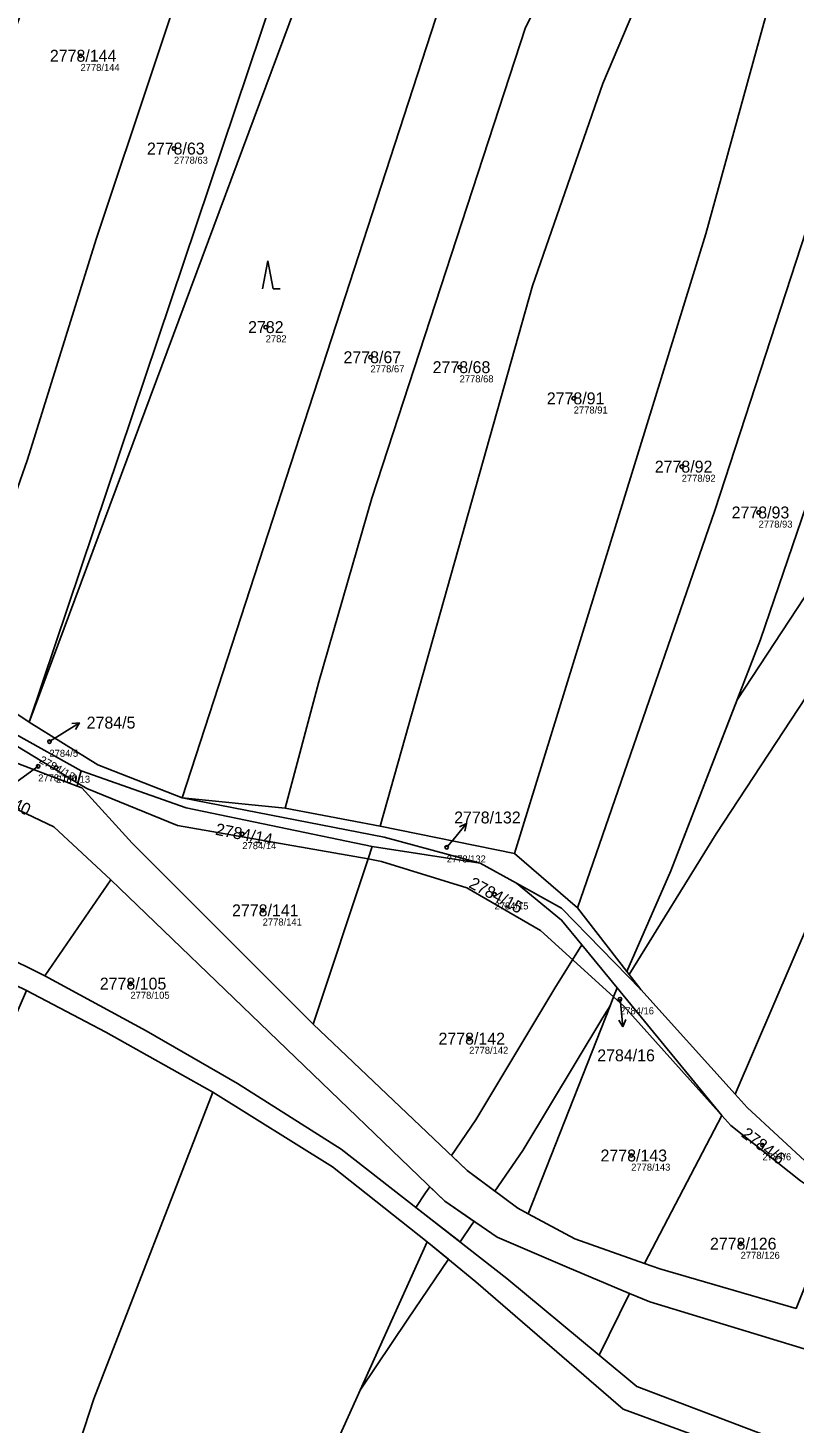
# Model space of a CAD drawing. Extents: x -739214 to -733252, y -1147612 to -1142842.
# Drawn here: x -737800.8 to -737691.6, y -1144174.3 to -1143975.5 of the extents above; entities that cross this region are included whole.
import ezdxf

# ---------------------------------------------------------------- set-up
doc = ezdxf.new("R2010")
doc.units = 0
for name, color, linetype in [('Definiční body', 7, 'Continuous'), ('Hranice parcel', 7, 'Continuous'), ('Parcelní čísla', 7, 'Continuous'), ('Polygon parcely', 7, 'Continuous'), ('Pop  PČ popisy', 7, 'Continuous'), ('Věcná břemena k části', 7, 'Continuous'), ('Značky kultur', 7, 'Continuous')]:
    doc.layers.add(name, color=color, linetype=linetype)

msp = doc.modelspace()

# ---------------------------------------------------------------- linework, layer by layer
at = {"layer": 'Definiční body'}
for centre in [(-737793.3, -1143979.46), (-737779.98, -1143992.68), (-737766.9, -1144018.12), (-737751.97, -1144022.41), (-737739.26, -1144023.83), (-737722.99, -1144028.27), (-737707.6, -1144038), (-737696.64, -1144044.53), (-737797.73, -1144077.18), (-737799.33, -1144080.69), (-737796.77, -1144080.88), (-737770.23, -1144090.34), (-737741.1, -1144092.24), (-737734.28, -1144098.93), (-737767.33, -1144101.22), (-737786.18, -1144111.66), (-737716.39, -1144113.87), (-737737.9, -1144119.5), (-737696.09, -1144134.67), (-737714.8, -1144136.15), (-737699.2, -1144148.71)]:
    msp.add_circle(centre, 0.25, dxfattribs=at)
at = {"layer": 'Hranice parcel'}
for p, q in [((-737811.43, -1144067.17), (-737800.62, -1144074.4)), ((-737802.59, -1144076.13), (-737793.21, -1144081.36)), ((-737793.79, -1144083.52), (-737803.83, -1144079.68)), ((-737793.68, -1144083.1), (-737793.21, -1144081.36)), ((-737793.79, -1144083.52), (-737793.68, -1144083.1)), ((-737778.79, -1144085.17), (-737764.11, -1144086.64)), ((-737764.11, -1144086.64), (-737750.57, -1144089.22)), ((-737750.57, -1144089.22), (-737731.44, -1144093.11)), ((-737752.31, -1144093.9), (-737751.72, -1144092.12)), ((-737751.72, -1144092.12), (-737736.33, -1144094.49)), ((-737760.15, -1144117.43), (-737752.31, -1144093.9)), ((-737731.44, -1144093.11), (-737722.45, -1144100.88)), ((-737736.33, -1144094.49), (-737731.14, -1144097.37)), ((-737788.99, -1144096.86), (-737798.39, -1144110.57)), ((-737722.45, -1144100.88), (-737715.43, -1144109.92)), ((-737715.43, -1144109.92), (-737713.43, -1144112.5)), ((-737717.31, -1144113.54), (-737716.81, -1144112.26)), ((-737716.81, -1144112.26), (-737701.87, -1144130.45)), ((-737713.43, -1144112.5), (-737700, -1144127.4)), ((-737701.87, -1144130.45), (-737712.92, -1144151.53)), ((-737715.02, -1144155.79), (-737719.36, -1144164.62))]:
    msp.add_line(p, q, dxfattribs=at)
for points in [[(-737753.56, -1143903.8), (-737763.28, -1143926.88), (-737774.4, -1143955.62), (-737791.08, -1144005.6), (-737800.85, -1144036.99), (-737811.43, -1144067.17)], [(-737747.42, -1143922.86), (-737762.04, -1143959.68), (-737800.62, -1144074.4)], [(-737731.19, -1143947.35), (-737747.9, -1143931.07), (-737755.39, -1143952.93), (-737800.62, -1144074.4)], [(-737778.79, -1144085.17), (-737742.03, -1143972.22), (-737731.19, -1143947.35)], [(-737764.11, -1144086.64), (-737759.35, -1144068.64), (-737751.79, -1144042.48), (-737729.89, -1143975.41), (-737721.43, -1143958.8)], [(-737750.57, -1144089.22), (-737728.86, -1144012.23), (-737718.85, -1143983.41), (-737711.46, -1143966.05)], [(-737731.44, -1144093.11), (-737704.16, -1144004.85), (-737695.11, -1143972.07)], [(-737722.45, -1144100.88), (-737702.88, -1144044.25), (-737679.03, -1143971.13)], [(-737715.43, -1144109.92), (-737709.14, -1144095.6), (-737696.36, -1144062.61), (-737675.57, -1144001.73), (-737665.81, -1143976.37)], [(-737700, -1144127.4), (-737689.12, -1144102.09), (-737672.1, -1144058.13), (-737645.71, -1143987.25)], [(-737800.62, -1144074.4), (-737790.82, -1144080.48), (-737778.79, -1144085.17)], [(-737793.68, -1144083.1), (-737802.5, -1144077.72), (-737803.03, -1144077.38)], [(-737832.85, -1144079.76), (-737811.85, -1144082.35), (-737797.08, -1144089.32), (-737788.99, -1144096.86)], [(-737793.21, -1144081.36), (-737778.24, -1144086.59), (-737751.72, -1144092.12)], [(-737760.15, -1144117.43), (-737785.94, -1144091.63), (-737793.11, -1144083.78), (-737793.79, -1144083.52)], [(-737752.31, -1144093.9), (-737779.49, -1144089.11), (-737792.4, -1144083.88), (-737793.68, -1144083.1)], [(-737778.79, -1144085.17), (-737750.03, -1144090.8), (-737736.33, -1144094.49)], [(-737717.31, -1144113.54), (-737727.72, -1144104.11), (-737738.21, -1144097.99), (-737750.41, -1144094.24), (-737752.31, -1144093.9)], [(-737835.66, -1144095.81), (-737817.39, -1144101.13), (-737798.39, -1144110.57)], [(-737788.99, -1144096.86), (-737741.37, -1144142.66), (-737733.92, -1144147.79), (-737723.93, -1144152.08), (-737715.02, -1144155.79)], [(-737731.14, -1144097.37), (-737724.72, -1144100.93), (-737713.43, -1144112.5)], [(-737731.14, -1144097.37), (-737724.73, -1144102.6), (-737721.85, -1144106.12), (-737716.81, -1144112.26)], [(-737798.39, -1144110.57), (-737783.92, -1144118.4), (-737770.91, -1144125.89), (-737756.13, -1144135.24), (-737732.54, -1144153.66), (-737719.36, -1144164.62)], [(-737774.46, -1144127.14), (-737789.7, -1144118.58), (-737800.98, -1144112.63)], [(-737729.47, -1144144.45), (-737717.81, -1144114.82), (-737717.31, -1144113.54)], [(-737701.87, -1144130.45), (-737715.85, -1144114.86), (-737717.31, -1144113.54)], [(-737729.47, -1144144.45), (-737730.96, -1144143.65), (-737738.16, -1144138.28), (-737760.15, -1144117.43)], [(-737774.46, -1144127.14), (-737791.38, -1144170.83), (-737800.92, -1144199.98), (-737804.43, -1144210.47), (-737815.21, -1144249.95), (-737823.77, -1144273.2)], [(-737743.89, -1144148.46), (-737757.36, -1144137.78), (-737774.46, -1144127.14)], [(-737700, -1144127.4), (-737698.26, -1144129.33), (-737689.43, -1144137.46), (-737683.21, -1144141.42)], [(-737685.37, -1144143.26), (-737690.67, -1144139.74), (-737700.6, -1144131.87), (-737701.87, -1144130.45)], [(-737712.92, -1144151.53), (-737722.85, -1144148), (-737729.47, -1144144.45)], [(-737743.89, -1144148.46), (-737756.47, -1144176.32), (-737774.04, -1144228.79), (-737783.15, -1144260.28), (-737791.71, -1144292.95)], [(-737696.15, -1144179.54), (-737715.96, -1144172.28), (-737736.94, -1144154.13), (-737743.89, -1144148.46)], [(-737691.29, -1144157.94), (-737710.74, -1144152.3), (-737712.92, -1144151.53)], [(-737715.02, -1144155.79), (-737712.12, -1144156.99), (-737655.52, -1144174.25)], [(-737719.36, -1144164.62), (-737714.01, -1144169.07), (-737692.22, -1144177.34), (-737663.62, -1144194.63), (-737660.98, -1144196.62)]]:
    msp.add_lwpolyline(points, dxfattribs=at)
at = {"layer": 'Polygon parcely'}
for points in [[(-737811.43, -1144067.17), (-737800.85, -1144036.99), (-737791.08, -1144005.6), (-737774.4, -1143955.62), (-737763.28, -1143926.88), (-737753.56, -1143903.8), (-737751.85, -1143900.08), (-737765.42, -1143893.22), (-737789.14, -1143941.15), (-737795.02, -1143954.63), (-737822.47, -1144030.56), (-737830.99, -1144056.18)], [(-737811.43, -1144067.17), (-737800.62, -1144074.4), (-737762.04, -1143959.68), (-737747.42, -1143922.86), (-737743.4, -1143912.94), (-737753.56, -1143903.8), (-737763.28, -1143926.88), (-737774.4, -1143955.62), (-737791.08, -1144005.6), (-737800.85, -1144036.99)], [(-737762.04, -1143959.68), (-737800.62, -1144074.4), (-737755.39, -1143952.93), (-737747.9, -1143931.07), (-737731.19, -1143947.35), (-737741.28, -1143934.28), (-737738.88, -1143928.91), (-737747.42, -1143922.86)], [(-737790.82, -1144080.48), (-737778.79, -1144085.17), (-737742.03, -1143972.22), (-737731.19, -1143947.35), (-737747.9, -1143931.07), (-737755.39, -1143952.93), (-737800.62, -1144074.4)], [(-737751.79, -1144042.48), (-737729.89, -1143975.41), (-737721.43, -1143958.8), (-737722.24, -1143957.09), (-737725.62, -1143952.53), (-737731.19, -1143947.35), (-737742.03, -1143972.22), (-737778.79, -1144085.17), (-737764.11, -1144086.64), (-737759.35, -1144068.64)], [(-737750.57, -1144089.22), (-737728.86, -1144012.23), (-737718.85, -1143983.41), (-737711.46, -1143966.05), (-737721.43, -1143958.8), (-737729.89, -1143975.41), (-737751.79, -1144042.48), (-737759.35, -1144068.64), (-737764.11, -1144086.64)], [(-737731.44, -1144093.11), (-737704.16, -1144004.85), (-737695.11, -1143972.07), (-737711.46, -1143966.05), (-737718.85, -1143983.41), (-737728.86, -1144012.23), (-737750.57, -1144089.22)], [(-737702.88, -1144044.25), (-737679.03, -1143971.13), (-737695.11, -1143972.07), (-737704.16, -1144004.85), (-737731.44, -1144093.11), (-737722.45, -1144100.88)], [(-737709.14, -1144095.6), (-737696.36, -1144062.61), (-737675.57, -1144001.73), (-737665.81, -1143976.37), (-737665.1, -1143974.47), (-737679.03, -1143971.13), (-737702.88, -1144044.25), (-737722.45, -1144100.88), (-737715.43, -1144109.92)], [(-737713.43, -1144112.5), (-737700, -1144127.4), (-737689.12, -1144102.09), (-737672.1, -1144058.13), (-737645.71, -1143987.25), (-737665.81, -1143976.37), (-737675.57, -1144001.73), (-737696.36, -1144062.61), (-737709.14, -1144095.6), (-737715.43, -1144109.92)], [(-737683.21, -1144141.42), (-737660.95, -1144082.54), (-737639.25, -1144021.37), (-737628.56, -1143994.6), (-737645.71, -1143987.25), (-737672.1, -1144058.13), (-737689.12, -1144102.09), (-737700, -1144127.4), (-737698.26, -1144129.33), (-737689.43, -1144137.46)], [(-737778.24, -1144086.59), (-737751.72, -1144092.12), (-737736.33, -1144094.49), (-737750.03, -1144090.8), (-737778.79, -1144085.17), (-737790.82, -1144080.48), (-737800.62, -1144074.4), (-737811.43, -1144067.17), (-737842.67, -1144053.64), (-737864.22, -1144045.97), (-737882.61, -1144037.94), (-737882.88, -1144041.39), (-737864.57, -1144046.82), (-737843.51, -1144054.24), (-737837.39, -1144056.82), (-737827.23, -1144061.07), (-737814.21, -1144069.2), (-737802.59, -1144076.13), (-737793.21, -1144081.36)], [(-737793.68, -1144083.1), (-737793.21, -1144081.36), (-737802.59, -1144076.13), (-737803.03, -1144077.38), (-737802.5, -1144077.72)], [(-737802.5, -1144077.72), (-737803.03, -1144077.38), (-737803.83, -1144079.68), (-737793.79, -1144083.52), (-737793.68, -1144083.1)], [(-737798.39, -1144110.57), (-737788.99, -1144096.86), (-737797.08, -1144089.32), (-737811.85, -1144082.35), (-737832.85, -1144079.76), (-737835.66, -1144095.81), (-737817.39, -1144101.13)], [(-737751.72, -1144092.12), (-737778.24, -1144086.59), (-737793.21, -1144081.36), (-737793.68, -1144083.1), (-737792.4, -1144083.88), (-737779.49, -1144089.11), (-737752.31, -1144093.9)], [(-737752.31, -1144093.9), (-737779.49, -1144089.11), (-737792.4, -1144083.88), (-737793.68, -1144083.1), (-737793.79, -1144083.52), (-737793.11, -1144083.78), (-737785.94, -1144091.63), (-737760.15, -1144117.43)], [(-737731.14, -1144097.37), (-737724.72, -1144100.93), (-737713.43, -1144112.5), (-737715.43, -1144109.92), (-737722.45, -1144100.88), (-737731.44, -1144093.11), (-737750.57, -1144089.22), (-737764.11, -1144086.64), (-737778.79, -1144085.17), (-737750.03, -1144090.8), (-737736.33, -1144094.49)], [(-737717.31, -1144113.54), (-737716.81, -1144112.26), (-737721.85, -1144106.12), (-737724.73, -1144102.6), (-737731.14, -1144097.37), (-737736.33, -1144094.49), (-737751.72, -1144092.12), (-737752.31, -1144093.9), (-737750.41, -1144094.24), (-737738.21, -1144097.99), (-737727.72, -1144104.11)], [(-737738.21, -1144097.99), (-737750.41, -1144094.24), (-737752.31, -1144093.9), (-737760.15, -1144117.43), (-737738.16, -1144138.28), (-737730.96, -1144143.65), (-737729.47, -1144144.45), (-737717.81, -1144114.82), (-737717.31, -1144113.54), (-737727.72, -1144104.11)], [(-737756.13, -1144135.24), (-737732.54, -1144153.66), (-737719.36, -1144164.62), (-737715.02, -1144155.79), (-737723.93, -1144152.08), (-737733.92, -1144147.79), (-737741.37, -1144142.66), (-737788.99, -1144096.86), (-737798.39, -1144110.57), (-737783.92, -1144118.4), (-737770.91, -1144125.89)], [(-737721.85, -1144106.12), (-737716.81, -1144112.26), (-737701.87, -1144130.45), (-737700.6, -1144131.87), (-737690.67, -1144139.74), (-737685.37, -1144143.26), (-737684.11, -1144144.1), (-737651.57, -1144160.64), (-737668.68, -1144150.65), (-737683.21, -1144141.42), (-737689.43, -1144137.46), (-737698.26, -1144129.33), (-737700, -1144127.4), (-737713.43, -1144112.5), (-737724.72, -1144100.93), (-737731.14, -1144097.37), (-737724.73, -1144102.6)], [(-737774.46, -1144127.14), (-737789.7, -1144118.58), (-737800.98, -1144112.63), (-737814.3, -1144143.39), (-737823.93, -1144167.59), (-737831.77, -1144190.63), (-737843.78, -1144222.11), (-737853.81, -1144251.92), (-737839.18, -1144262.99), (-737823.77, -1144273.2), (-737815.21, -1144249.95), (-737804.43, -1144210.47), (-737800.92, -1144199.98), (-737791.38, -1144170.83)], [(-737701.87, -1144130.45), (-737715.85, -1144114.86), (-737717.31, -1144113.54), (-737717.81, -1144114.82), (-737729.47, -1144144.45), (-737722.85, -1144148), (-737712.92, -1144151.53)], [(-737717.31, -1144113.54), (-737715.85, -1144114.86), (-737701.87, -1144130.45), (-737716.81, -1144112.26)], [(-737823.77, -1144273.2), (-737809.7, -1144282.52), (-737791.71, -1144292.95), (-737783.15, -1144260.28), (-737774.04, -1144228.79), (-737756.47, -1144176.32), (-737743.89, -1144148.46), (-737757.36, -1144137.78), (-737774.46, -1144127.14), (-737791.38, -1144170.83), (-737800.92, -1144199.98), (-737804.43, -1144210.47), (-737815.21, -1144249.95)], [(-737685.37, -1144143.26), (-737690.67, -1144139.74), (-737700.6, -1144131.87), (-737701.87, -1144130.45), (-737712.92, -1144151.53), (-737710.74, -1144152.3), (-737691.29, -1144157.94)], [(-737736.94, -1144154.13), (-737743.89, -1144148.46), (-737756.47, -1144176.32), (-737774.04, -1144228.79), (-737783.15, -1144260.28), (-737791.71, -1144292.95), (-737777.16, -1144298.24), (-737750.46, -1144304.05), (-737741.14, -1144306.42), (-737735.31, -1144283.15), (-737727.76, -1144259.01), (-737718.72, -1144233.73), (-737702.56, -1144192.49), (-737696.15, -1144179.54), (-737715.96, -1144172.28)], [(-737714.01, -1144169.07), (-737692.22, -1144177.34), (-737663.62, -1144194.63), (-737660.98, -1144196.62), (-737659.48, -1144193), (-737656.33, -1144177.29), (-737655.52, -1144174.25), (-737712.12, -1144156.99), (-737715.02, -1144155.79), (-737719.36, -1144164.62)]]:
    msp.add_lwpolyline(points, close=True, dxfattribs=at)
for points in [[(-737964.98, -1144037.92), (-737934.66, -1144053.55), (-737929.32, -1144055.23), (-737923.72, -1144055.39), (-737913.71, -1144055.05), (-737905.24, -1144054.77), (-737901.35, -1144056.29), (-737898.05, -1144058.59), (-737885.4, -1144069.1), (-737883.75, -1144069.88), (-737873.47, -1144074.76), (-737832.85, -1144079.76), (-737811.85, -1144082.35), (-737797.08, -1144089.32), (-737788.99, -1144096.86), (-737741.37, -1144142.66), (-737733.92, -1144147.79), (-737723.93, -1144152.08), (-737715.02, -1144155.79), (-737712.12, -1144156.99), (-737655.52, -1144174.25)], [(-737692.22, -1144177.34), (-737714.01, -1144169.07), (-737719.36, -1144164.62), (-737732.54, -1144153.66), (-737756.13, -1144135.24), (-737770.91, -1144125.89), (-737783.92, -1144118.4), (-737798.39, -1144110.57), (-737817.39, -1144101.13), (-737835.66, -1144095.81), (-737868.18, -1144087.54), (-737889.25, -1144085.28), (-737892.12, -1144085.08), (-737914.29, -1144076.59), (-737932.49, -1144068.97), (-737944.21, -1144063.75)], [(-737949.57, -1144066.24), (-737919.88, -1144077.7), (-737891.15, -1144088.14), (-737868.79, -1144090.89), (-737851.64, -1144094.91), (-737818.97, -1144103.97), (-737800.98, -1144112.63), (-737789.7, -1144118.58), (-737774.46, -1144127.14), (-737757.36, -1144137.78), (-737743.89, -1144148.46), (-737736.94, -1144154.13), (-737715.96, -1144172.28), (-737696.15, -1144179.54)], [(-737691.29, -1144157.94), (-737710.74, -1144152.3), (-737712.92, -1144151.53), (-737722.85, -1144148), (-737729.47, -1144144.45), (-737730.96, -1144143.65), (-737738.16, -1144138.28), (-737760.15, -1144117.43), (-737785.94, -1144091.63), (-737793.11, -1144083.78), (-737793.79, -1144083.52), (-737803.83, -1144079.68)]]:
    msp.add_lwpolyline(points, dxfattribs=at)
at = {"layer": 'Pop  PČ popisy'}
for p, q in [((-737797.73, -1144077.18), (-737795.96, -1144076.07)), ((-737795.96, -1144076.07), (-737793.42, -1144074.48)), ((-737793.42, -1144074.48), (-737794.53, -1144074.59)), ((-737793.42, -1144074.48), (-737794, -1144075.44)), ((-737799.9, -1144081.1), (-737802.33, -1144082.86)), ((-737799.33, -1144080.69), (-737799.9, -1144081.1)), ((-737740.19, -1144091.15), (-737738.26, -1144088.85)), ((-737738.26, -1144088.85), (-737739.29, -1144089.3)), ((-737738.26, -1144088.85), (-737738.52, -1144089.94)), ((-737741.1, -1144092.24), (-737740.19, -1144091.15)), ((-737716.39, -1144113.87), (-737716.29, -1144114.83)), ((-737716.29, -1144114.83), (-737715.98, -1144117.81)), ((-737715.98, -1144117.81), (-737716.58, -1144116.87)), ((-737715.98, -1144117.81), (-737715.58, -1144116.77))]:
    msp.add_line(p, q, dxfattribs=at)
at = {"layer": 'Věcná břemena k části'}
for points in [[(-737702.69, -1144090.34), (-737669.66, -1144040.07), (-737659.82, -1144025.16), (-737647.4, -1143991.8), (-737676.34, -1144035.67), (-737699.7, -1144071.22), (-737709.14, -1144095.6), (-737715.43, -1144109.92), (-737715.07, -1144110.38)], [(-737730.24, -1144135.42), (-737718.84, -1144116.48), (-737717.81, -1144114.82), (-737717.31, -1144113.54), (-737716.81, -1144112.26), (-737721.85, -1144106.12), (-737725.68, -1144112.32), (-737736.96, -1144131.08), (-737740.43, -1144136.13), (-737738.16, -1144138.28), (-737734.23, -1144141.21)], [(-737737.52, -1144145.99), (-737737.2, -1144145.53), (-737741.37, -1144142.66), (-737743.51, -1144140.6), (-737744.12, -1144141.49), (-737745.51, -1144143.54), (-737739.19, -1144148.47)], [(-737746.63, -1144159.48), (-737740.85, -1144150.94), (-737743.89, -1144148.46), (-737753.43, -1144169.6)]]:
    msp.add_lwpolyline(points, close=True, dxfattribs=at)
at = {"layer": 'Značky kultur'}
for p, q in [((-737766.6, -1144008.67), (-737767.35, -1144012.67)), ((-737765.85, -1144012.67), (-737766.6, -1144008.67)), ((-737765.85, -1144012.67), (-737764.85, -1144012.67))]:
    msp.add_line(p, q, dxfattribs=at)

# ---------------------------------------------------------------- texts
at = {"layer": 'Definiční body'}
for s, p in [('2778/144', (-737793.3, -1143981.62)), ('2778/63', (-737779.98, -1143994.84)), ('2782', (-737766.9, -1144020.28)), ('2778/67', (-737751.97, -1144024.57)), ('2778/68', (-737739.26, -1144025.99)), ('2778/91', (-737722.99, -1144030.43)), ('2778/92', (-737707.6, -1144040.16)), ('2778/93', (-737696.64, -1144046.69)), ('2784/5', (-737797.73, -1144079.34)), ('2778/140', (-737799.33, -1144082.85)), ('2784/13', (-737796.77, -1144083.04)), ('2784/14', (-737770.23, -1144092.5)), ('2778/132', (-737741.1, -1144094.4)), ('2784/15', (-737734.28, -1144101.09)), ('2778/141', (-737767.33, -1144103.38)), ('2778/105', (-737786.18, -1144113.82)), ('2784/16', (-737716.39, -1144116.03)), ('2778/142', (-737737.9, -1144121.66)), ('2784/6', (-737696.09, -1144136.83)), ('2778/143', (-737714.8, -1144138.31)), ('2778/126', (-737699.2, -1144150.87))]:
    msp.add_text(s, height=1, dxfattribs=at).set_placement(p)
at = {"layer": 'Parcelní čísla'}
for s, p in [('2778/144', (-737797.67, -1143980.31)), ('2778/63', (-737783.82, -1143993.53)), ('2782', (-737769.41, -1144018.97)), ('2778/67', (-737755.81, -1144023.26)), ('2778/68', (-737743.1, -1144024.68)), ('2778/91', (-737726.83, -1144029.12)), ('2778/92', (-737711.44, -1144038.85)), ('2778/93', (-737700.48, -1144045.38)), ('2784/5', (-737792.42, -1144075.32)), ('2778/132', (-737740.04, -1144088.84)), ('2778/141', (-737771.7, -1144102.07)), ('2778/105', (-737790.55, -1144112.51)), ('2778/142', (-737742.27, -1144120.35)), ('2784/16', (-737719.64, -1144122.73)), ('2778/143', (-737719.17, -1144137)), ('2778/126', (-737703.57, -1144149.56))]:
    msp.add_text(s, height=1.7, dxfattribs=at).set_placement(p)
for s, height, rotation, p in [('2784/13', 1.14, 331, (-737799.3, -1144080.13)), ('2778/140', 1.7, 335, (-737809.5, -1144083.76)), ('2784/14', 1.7, 349, (-737774.16, -1144090.44)), ('2784/15', 1.7, 332, (-737738.07, -1144097.88)), ('2784/6', 1.7, 323, (-737699.24, -1144133.36))]:
    msp.add_text(s, height=height, rotation=rotation, dxfattribs=at).set_placement(p)

doc.saveas('drawing.dxf')
